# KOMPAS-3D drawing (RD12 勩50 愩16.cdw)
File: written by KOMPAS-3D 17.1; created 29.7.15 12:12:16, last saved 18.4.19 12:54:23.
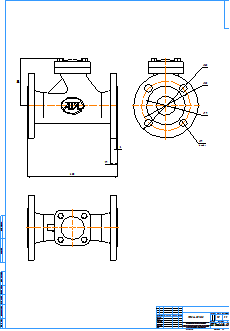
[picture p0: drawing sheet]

Sheet 1: A1, portrait

Title block, sheet 1: name: RD12 Ду50 Ру16; material: Внимание! Данный продукт является объектом авторского права ООО «Торговый Дом АДЛ». / Запрещается изменение, копирование, распространение / (в том числе путем копирования на другие сайты и ресурсы в Интернете) / или любое иное использование информации и объектов без предварительного / согласия правообладателя (ООО «Торговый Дом АДЛ»).; mass: 10; sheets: 1; organisation: ООО "Торговый дом АДЛ"; sheet format: A1; stored path: \\adlc.lan\data\АДЛ_ПКД\3D-модели\ADL production\Клапаны обратные ГРАНЛОК\RD12\KOMPAS 2D\RD12 Ду50 Ру16.cdw

Views: Вид 1, Проекционный вид 2, Проекционный вид 3
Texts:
  Klimkovich
  ADL
Dimensions and other numbers on the sheet: 230; 19; 3; 120; 165; 125; 99; 4 отв.; 1:1; 1; 10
